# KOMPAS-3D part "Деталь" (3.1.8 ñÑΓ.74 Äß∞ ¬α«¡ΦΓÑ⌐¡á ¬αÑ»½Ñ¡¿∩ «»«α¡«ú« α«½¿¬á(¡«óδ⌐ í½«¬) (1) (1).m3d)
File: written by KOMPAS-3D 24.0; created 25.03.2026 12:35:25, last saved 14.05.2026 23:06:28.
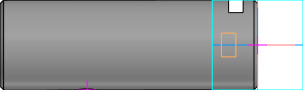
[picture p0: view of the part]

Document properties: Автор: TMK; Полное имя файла: E:\test_kompas\all_v22\3.1.8 дет.74 Ось кронштейна крепления опорного ролика(новый блок) (1) (1).m3d; Организация: TMK

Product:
- Part/product: Деталь
    Масса: 2.046242

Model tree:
1. Эскиз:1
2. Элемент выдавливания:1
     Расстояние 2 = 142
3. Фаска:1  (with: Ребро.Элемент выдавливания:1)
     Угол = 45; Длина 1 = 2; Длина 2 = 2
4. Эскиз:2
5. Отверстие:2  (with: Грань.Элемент выдавливания:1)
     Глубина выреза = 99.5; Диаметр отверстия = 11.4448; Угол конуса дна = 118; Диаметр цековки = 23; Глубина цековки = 12
6. G 1/4  (with: Грань.Отверстие:2)
     Длина резьбы = 20; Шаг резьбы = 1.337; Номинальный диаметр резьбы = 13.157
7. Фаска:2  (with: Ребро.Отверстие:2)
     Угол = 45; Длина 1 = 1.6; Длина 2 = 1.6
8. Смещенная плоскость:2
     Расстояние = 25
9. Эскиз:4
10. Отверстие:3
     Глубина выреза = 30.5; Диаметр отверстия = 11.5; Угол конуса дна = 118; Расстояние 2 = -94
11. Смещенная плоскость:3
     Расстояние = 25
12. Эскиз:5
13. Элемент выдавливания:3
     Расстояние 2 = 50

Expressions: cil2_6357-81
